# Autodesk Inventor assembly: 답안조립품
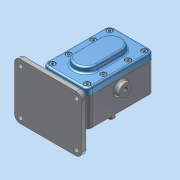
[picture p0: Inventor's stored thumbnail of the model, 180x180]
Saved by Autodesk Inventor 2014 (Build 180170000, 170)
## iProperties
Created: 2026-10
Part Number: 답안조립품
Document SubType Name: Assembly
Designer: dg
Author: dg
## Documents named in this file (11)
- C:\Users\dg\Desktop\761003V1010\답안조립품.iam
- C:\Users\dg\Desktop\761003V1010\본체.ipt
- C:\Users\dg\Desktop\761003V1010\가져온 구성요소\6각 구멍붙이 볼트 M5x16\6각 구멍붙이 볼트 M5x16.ipt
- C:\Users\dg\Desktop\761003V1010\가져온 구성요소\개스킷\개스킷.ipt
- C:\Users\dg\Desktop\761003V1010\가져온 구성요소\구동 축\구동 축.ipt
- C:\Users\dg\Desktop\761003V1010\가져온 구성요소\베어링 부시\베어링 부시.ipt
- C:\Users\dg\Desktop\761003V1010\가져온 구성요소\스퍼 기어\스퍼 기어.ipt
- C:\Users\dg\Desktop\761003V1010\가져온 구성요소\오일 실 16 28 7\오일 실 16 28 7.ipt
- C:\Users\dg\Desktop\761003V1010\가져온 구성요소\종동 축\종동 축.ipt
- C:\Users\dg\Desktop\761003V1010\가져온 구성요소\커버\커버.ipt
- C:\Users\dg\Desktop\761003V1010\가져온 구성요소\평행 키 6x6x18\평행 키 6x6x18.ipt
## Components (10 placed, 3 different names)
1. 6각 구멍붙이 볼트 M5x16:1
2. 개스킷:1
3. 구동 축:1
4. 6각 구멍붙이 볼트 M5x16:2
5. 6각 구멍붙이 볼트 M5x16:3
6. 6각 구멍붙이 볼트 M5x16:4
7. 6각 구멍붙이 볼트 M5x16:5
8. 6각 구멍붙이 볼트 M5x16:6
9. 6각 구멍붙이 볼트 M5x16:7
10. 6각 구멍붙이 볼트 M5x16:8
